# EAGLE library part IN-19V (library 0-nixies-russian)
IN-19V: medium symbol frontview nixie tube
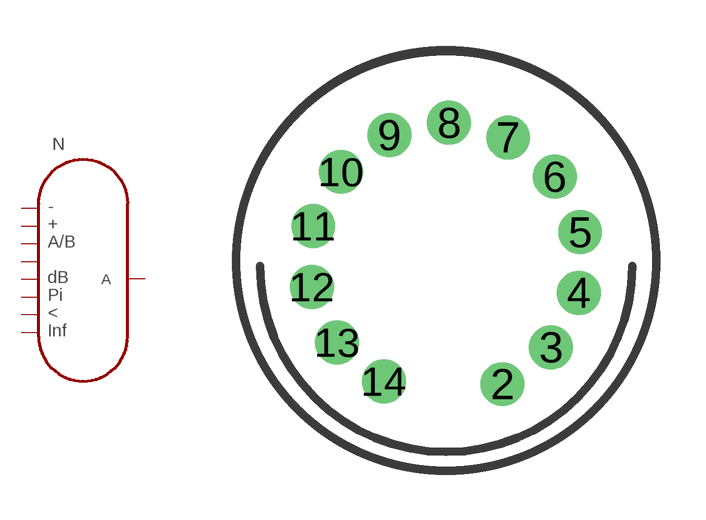
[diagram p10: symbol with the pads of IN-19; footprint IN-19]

Designator prefix N

## IN-19V  [IN-19]
2  P$6
4  P$3
5  P$8
6  P$7
8  A
10  P$1
11  P$4
12  P$2
14  P$5

## Footprint IN-19 (pad centres in mm)
drill 0.84 round: 2 1.733,-3.786; 3 3.222,-2.652; 4 4.072,-0.985; 5 4.114,0.886; 6 3.34,2.59; 7 1.903,3.79; 8 0.089,4.247; 9 -1.745,3.872; 10 -3.234,2.738; 11 -4.084,1.07; 12 -4.126,-0.801; 13 -3.352,-2.505; 14 -1.915,-3.704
